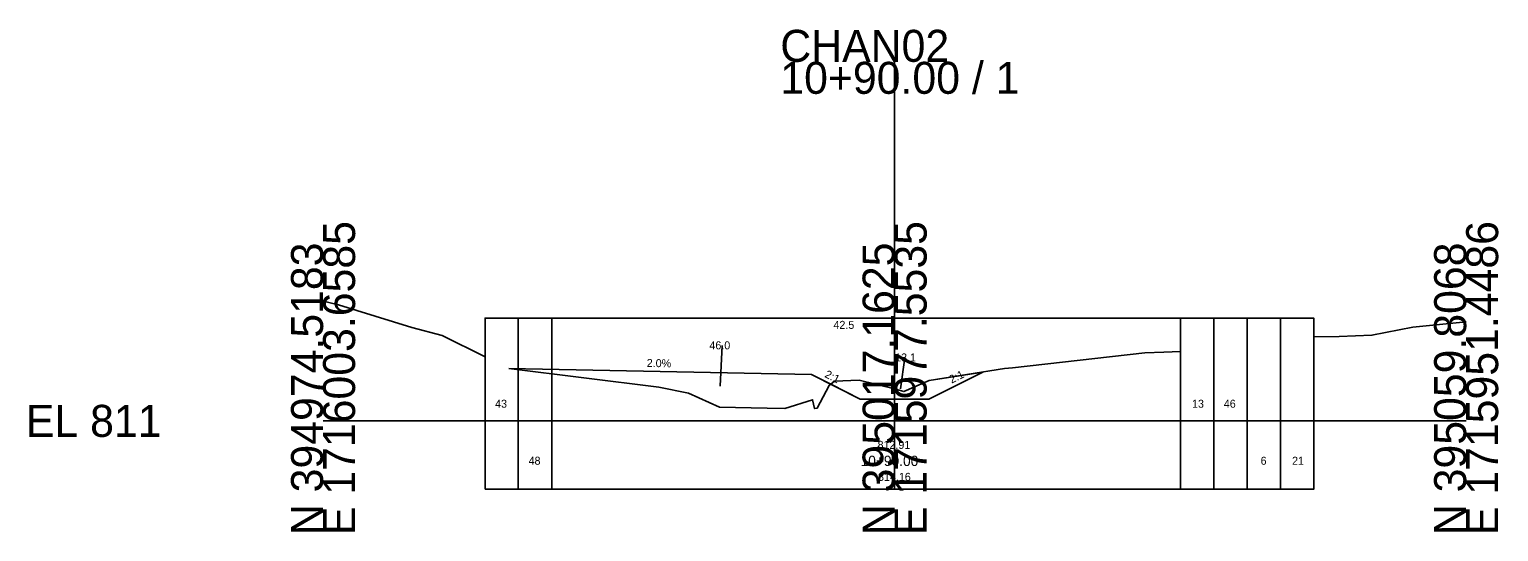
# Model space of a CAD drawing. Extents: x -26 to 103, y -10 to 16052.
# Drawn here: x -25.7 to 102.8, y 10990.3 to 11034.3 of the extents above; entities that cross this region are included whole.
import ezdxf

# ---------------------------------------------------------------- set-up
doc = ezdxf.new("R2010")
doc.units = 0
for name, color, linetype in [('GK_Cells', 7, 'Continuous'), ('SH_Text', 7, 'Continuous'), ('XS_P_Annotation', 7, 'Continuous'), ('XS_P_Boundary', 7, 'Continuous'), ('XS_P_Earthwork_Shapes', 7, 'Continuous'), ('XS_P_Finished_Grade', 7, 'Continuous'), ('XS_X_Ground_Line', 7, 'Continuous')]:
    doc.layers.add(name, color=color, linetype=linetype)

msp = doc.modelspace()

# ---------------------------------------------------------------- linework, layer by layer
at = {"layer": 'GK_Cells'}
for p, q in [((50, 11000), (50, 11031.42)), ((0, 11000), (50, 11000)), ((50, 11000), (100, 11000))]:
    msp.add_line(p, q, dxfattribs=at)
at = {"layer": 'XS_P_Boundary'}
for p, q in [((17.08, 10994.01), (17.08, 11008.99)), ((20, 10994.01), (20, 11008.99)), ((50, 10994.01), (50, 11008.99)), ((75, 10994.01), (75, 11008.99)), ((77.92, 10994.01), (77.92, 11008.99)), ((80.83, 10994.01), (80.83, 11008.99)), ((83.75, 10994.01), (83.75, 11008.99)), ((15.63, 11001.5), (15.63, 11001.5)), ((76.46, 11001.5), (76.46, 11001.5)), ((79.38, 11001.5), (79.38, 11001.5)), ((18.54, 10996.51), (18.54, 10996.51)), ((82.29, 10996.51), (82.29, 10996.51)), ((85.21, 10996.51), (85.21, 10996.51))]:
    msp.add_line(p, q, dxfattribs=at)
msp.add_lwpolyline([(14.17, 10994.01), (14.17, 11008.99), (86.67, 11008.99), (86.67, 10994.01)], close=True, dxfattribs=at)
at = {"layer": 'XS_P_Earthwork_Shapes'}
for p, q in [((34.74, 11003.04), (34.92, 11006.61)), ((50.52, 11002.8), (50.9, 11005.55)), ((42.73, 11004.05), (16.26, 11004.57)), ((44.41, 11003.21), (42.73, 11004.05)), ((53, 11001.91), (57.71, 11004.26)), ((57.71, 11004.26), (53.01, 11003.52)), ((44.41, 11003.21), (47, 11001.91)), ((47, 11001.91), (53, 11001.91))]:
    msp.add_line(p, q, dxfattribs=at)
for points in [[(16.26, 11004.57), (29.36, 11002.94), (31.98, 11002.41), (34.67, 11001.19), (38.86, 11001.1), (40.4, 11001.08), (42.82, 11001.85), (43, 11001.08), (43.23, 11001.12), (44.27, 11003.1), (44.41, 11003.21)], [(16.26, 11004.57), (42.73, 11004.05), (47, 11001.91), (53, 11001.91), (57.71, 11004.26)], [(53.01, 11003.52), (50.8, 11002.56), (50, 11002.8), (46.9, 11003.56), (44.75, 11003.48), (44.41, 11003.21)]]:
    msp.add_lwpolyline(points, dxfattribs=at)
at = {"layer": 'XS_P_Finished_Grade'}
for p, q in [((42.73, 11004.05), (16.26, 11004.57)), ((42.73, 11004.05), (47, 11001.91)), ((57.71, 11004.26), (53, 11001.91)), ((47, 11001.91), (53, 11001.91))]:
    msp.add_line(p, q, dxfattribs=at)
at = {"layer": 'XS_X_Ground_Line'}
for points in [[(0, 11010.47), (1.34, 11010.15), (7.76, 11008.16), (10.41, 11007.48), (14.17, 11005.59)], [(86.67, 11007.36), (88.88, 11007.39), (91.75, 11007.49), (95.34, 11008.19), (100, 11008.68)], [(16.26, 11004.57), (29.36, 11002.94), (31.98, 11002.41), (34.67, 11001.19), (38.86, 11001.1), (40.4, 11001.08), (42.82, 11001.85), (43, 11001.08), (43.23, 11001.12), (44.27, 11003.1), (44.75, 11003.48), (46.9, 11003.56), (50, 11002.8), (50.8, 11002.56), (53.01, 11003.52), (59.62, 11004.57), (60.31, 11004.65), (71.88, 11005.96), (73.54, 11006), (75, 11006.06)]]:
    msp.add_lwpolyline(points, dxfattribs=at)

# ---------------------------------------------------------------- texts
at = {"layer": 'GK_Cells'}
for s, p in [('CHAN02', (40, 11031.42)), ('10+90.00 / 1', (40, 11028.62)), ('EL 811', (-26, 10998.6))]:
    msp.add_text(s, height=2.8, dxfattribs=at).set_placement(p)
for s, p in [('E 1716003.6585', (2.8, 10990)), ('E 1715977.5535', (52.8, 10990)), ('E 1715951.4486', (102.8, 10990)), ('N 394974.5183', (0, 10990)), ('N 395017.1625', (50, 10990)), ('N 395059.8068', (100, 10990))]:
    msp.add_text(s, height=2.8, rotation=90, dxfattribs=at).set_placement(p)
at = {"layer": 'SH_Text'}
for s, p in [('43', (15.05, 11001.15)), ('13', (76.02, 11001.15)), ('46', (78.8, 11001.15)), ('48', (17.98, 10996.16)), ('6', (82.02, 10996.16)), ('21', (84.77, 10996.16))]:
    msp.add_text(s, height=0.7, dxfattribs=at).set_placement(p)
at = {"layer": 'XS_P_Annotation'}
for s, rotation, p in [('2.0%', 358.8542, (28.31, 11004.72)), ('2:1', 333.4349, (43.82, 11003.85)), ('2:1', 26.5651, (54.99, 11003.26))]:
    msp.add_text(s, height=0.7, rotation=rotation, dxfattribs=at).set_placement(p)
for s, height, p in [('812.91', 0.7, (48.51, 10997.55)), ('10+90.00', 0.9, (47.02, 10996.05)), ('814.16', 0.7, (48.55, 10994.75))]:
    msp.add_text(s, height=height, dxfattribs=at).set_placement(p)
at = {"layer": 'XS_P_Earthwork_Shapes'}
for s, p in [('42.5', (44.65, 11008.05)), ('46.0', (33.8, 11006.26)), ('13.1', (50.05, 11005.2))]:
    msp.add_text(s, height=0.7, dxfattribs=at).set_placement(p)

doc.saveas('drawing.dxf')
